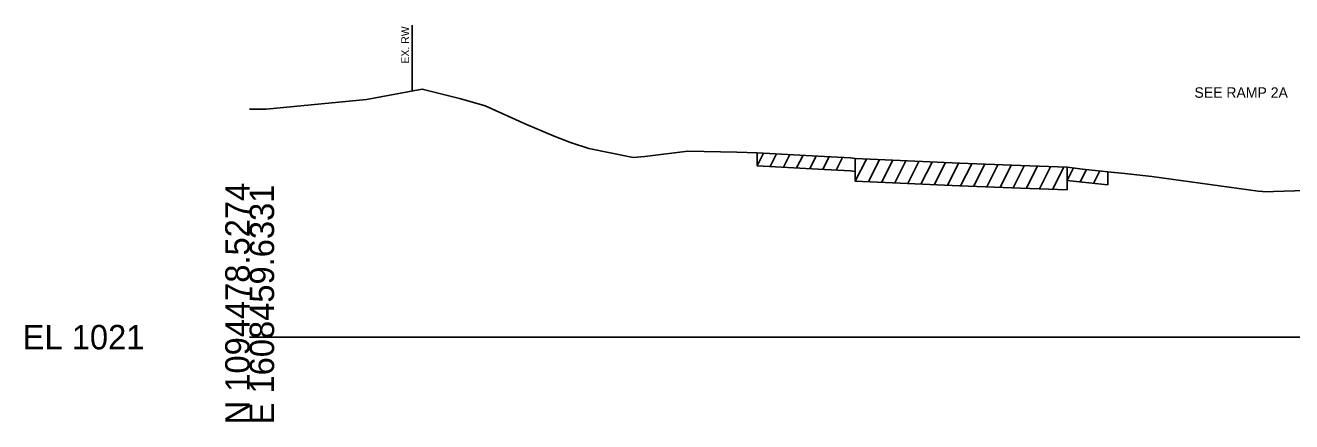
# Model space of a CAD drawing. Extents: x -26 to 1614813, y -18 to 1100051.
# Drawn here: x 3974.3 to 4119.3, y 9490.3 to 9535.7 of the extents above; entities that cross this region are included whole.
import ezdxf

# ---------------------------------------------------------------- set-up
doc = ezdxf.new("R2010")
doc.units = 0
for name, color, linetype in [('RD_EX_Misc', 7, 'Continuous'), ('RD_GPK_XS_Cell', 7, 'Continuous'), ('RD_Sketch1', 7, 'Continuous'), ('RD_XS_ExGround', 7, 'Continuous'), ('RD_XS_ExPaveRet', 7, 'Continuous'), ('RD_XS_ExRW', 7, 'Continuous'), ('RD_XS_TX_Notes', 7, 'Continuous')]:
    doc.layers.add(name, color=color, linetype=linetype)

msp = doc.modelspace()

# ---------------------------------------------------------------- linework, layer by layer
at = {"layer": 'RD_EX_Misc'}
for p, q in [((4058.12, 9519.64), (4058.12, 9521.14)), ((4069.36, 9520.48), (4069.36, 9518.98)), ((4058.12, 9519.64), (4065.11, 9519.26)), ((4065.11, 9519.26), (4068.82, 9519.07)), ((4068.82, 9519.07), (4069.36, 9518.98)), ((4093.63, 9517.97), (4093.63, 9519.47)), ((4098.29, 9518.95), (4098.29, 9517.45)), ((4093.63, 9517.97), (4095.38, 9517.77)), ((4095.38, 9517.77), (4098.29, 9517.45)), ((4098.29, 9517.45), (4098.29, 9517.45))]:
    msp.add_line(p, q, dxfattribs=at)
at = {"layer": 'RD_GPK_XS_Cell'}
msp.add_line((4000, 9500), (4175, 9500), dxfattribs=at)
at = {"layer": 'RD_Sketch1'}
for p, q in [((4058.12, 9519.64), (4058.85, 9521.1)), ((4059.63, 9519.55), (4060.36, 9521.01)), ((4061.13, 9519.47), (4061.87, 9520.93)), ((4062.64, 9519.39), (4063.38, 9520.85)), ((4064.15, 9519.31), (4064.88, 9520.77)), ((4065.66, 9519.23), (4066.39, 9520.69)), ((4067.17, 9519.15), (4067.9, 9520.61)), ((4093.63, 9517.97), (4094.34, 9519.39)), ((4095.14, 9517.8), (4095.85, 9519.22)), ((4096.64, 9517.63), (4097.36, 9519.05))]:
    msp.add_line(p, q, dxfattribs=at)
at = {"layer": 'RD_XS_ExGround'}
msp.add_lwpolyline([(4000, 9526.15), (4001.88, 9526.13), (4013.38, 9527.25), (4019.77, 9528.44), (4024.17, 9527.3), (4026.99, 9526.51), (4031.64, 9524.42), (4034.87, 9523.04), (4036.73, 9522.3), (4038.84, 9521.63), (4043.92, 9520.61), (4045.27, 9520.7), (4050.2, 9521.32), (4055.81, 9521.19), (4058.12, 9521.14), (4065.11, 9520.76), (4068.82, 9520.57), (4069.36, 9520.48), (4075.34, 9520.2), (4081.32, 9519.94), (4088.3, 9519.67), (4093.63, 9519.47), (4095.38, 9519.27), (4098.29, 9518.95), (4100.23, 9518.75), (4103.32, 9518.41), (4115.51, 9516.75), (4116.06, 9516.68), (4116.06, 9516.66), (4124.54, 9516.94)], dxfattribs=at)
at = {"layer": 'RD_XS_ExPaveRet'}
for p, q in [((4069.36, 9517.88), (4069.36, 9520.48)), ((4069.36, 9517.88), (4070.64, 9520.42)), ((4070.87, 9517.81), (4072.14, 9520.35)), ((4072.37, 9517.74), (4073.65, 9520.28)), ((4073.88, 9517.67), (4075.16, 9520.21)), ((4075.39, 9517.6), (4076.66, 9520.14)), ((4076.89, 9517.53), (4078.17, 9520.07)), ((4078.4, 9517.46), (4079.68, 9520.01)), ((4079.91, 9517.4), (4081.19, 9519.94)), ((4081.42, 9517.33), (4082.7, 9519.88)), ((4082.92, 9517.27), (4084.2, 9519.83)), ((4084.43, 9517.22), (4085.71, 9519.77)), ((4085.94, 9517.16), (4087.22, 9519.71)), ((4087.44, 9517.1), (4088.72, 9519.65)), ((4088.95, 9517.05), (4090.23, 9519.6)), ((4090.46, 9516.99), (4091.74, 9519.54)), ((4091.96, 9516.93), (4093.25, 9519.49)), ((4093.63, 9519.47), (4093.63, 9516.87)), ((4069.36, 9517.88), (4075.34, 9517.6)), ((4069.36, 9517.88), (4069.36, 9517.88)), ((4075.34, 9517.6), (4081.32, 9517.34)), ((4081.32, 9517.34), (4088.3, 9517.07)), ((4088.3, 9517.07), (4093.63, 9516.87)), ((4093.63, 9516.87), (4093.63, 9516.87))]:
    msp.add_line(p, q, dxfattribs=at)
at = {"layer": 'RD_XS_ExRW'}
msp.add_line((4018.62, 9535.75), (4018.62, 9528.23), dxfattribs=at)

# ---------------------------------------------------------------- texts
at = {"layer": 'RD_GPK_XS_Cell'}
for s, p in [('N 1094478.5274', (4000, 9490)), ('E 1608459.6331', (4002.8, 9490))]:
    msp.add_text(s, height=2.8, rotation=90, dxfattribs=at).set_placement(p)
msp.add_text('EL 1021', height=2.8, dxfattribs=at).set_placement((3974, 9498.6))
at = {"layer": 'RD_XS_ExRW'}
msp.add_text('EX. RW', height=0.9, rotation=90, dxfattribs=at).set_placement((4018.26, 9531.35))
at = {"layer": 'RD_XS_TX_Notes'}
msp.add_text('SEE RAMP 2A', height=1.2, dxfattribs=at).set_placement((4108.21, 9527.44))

doc.saveas('drawing.dxf')
